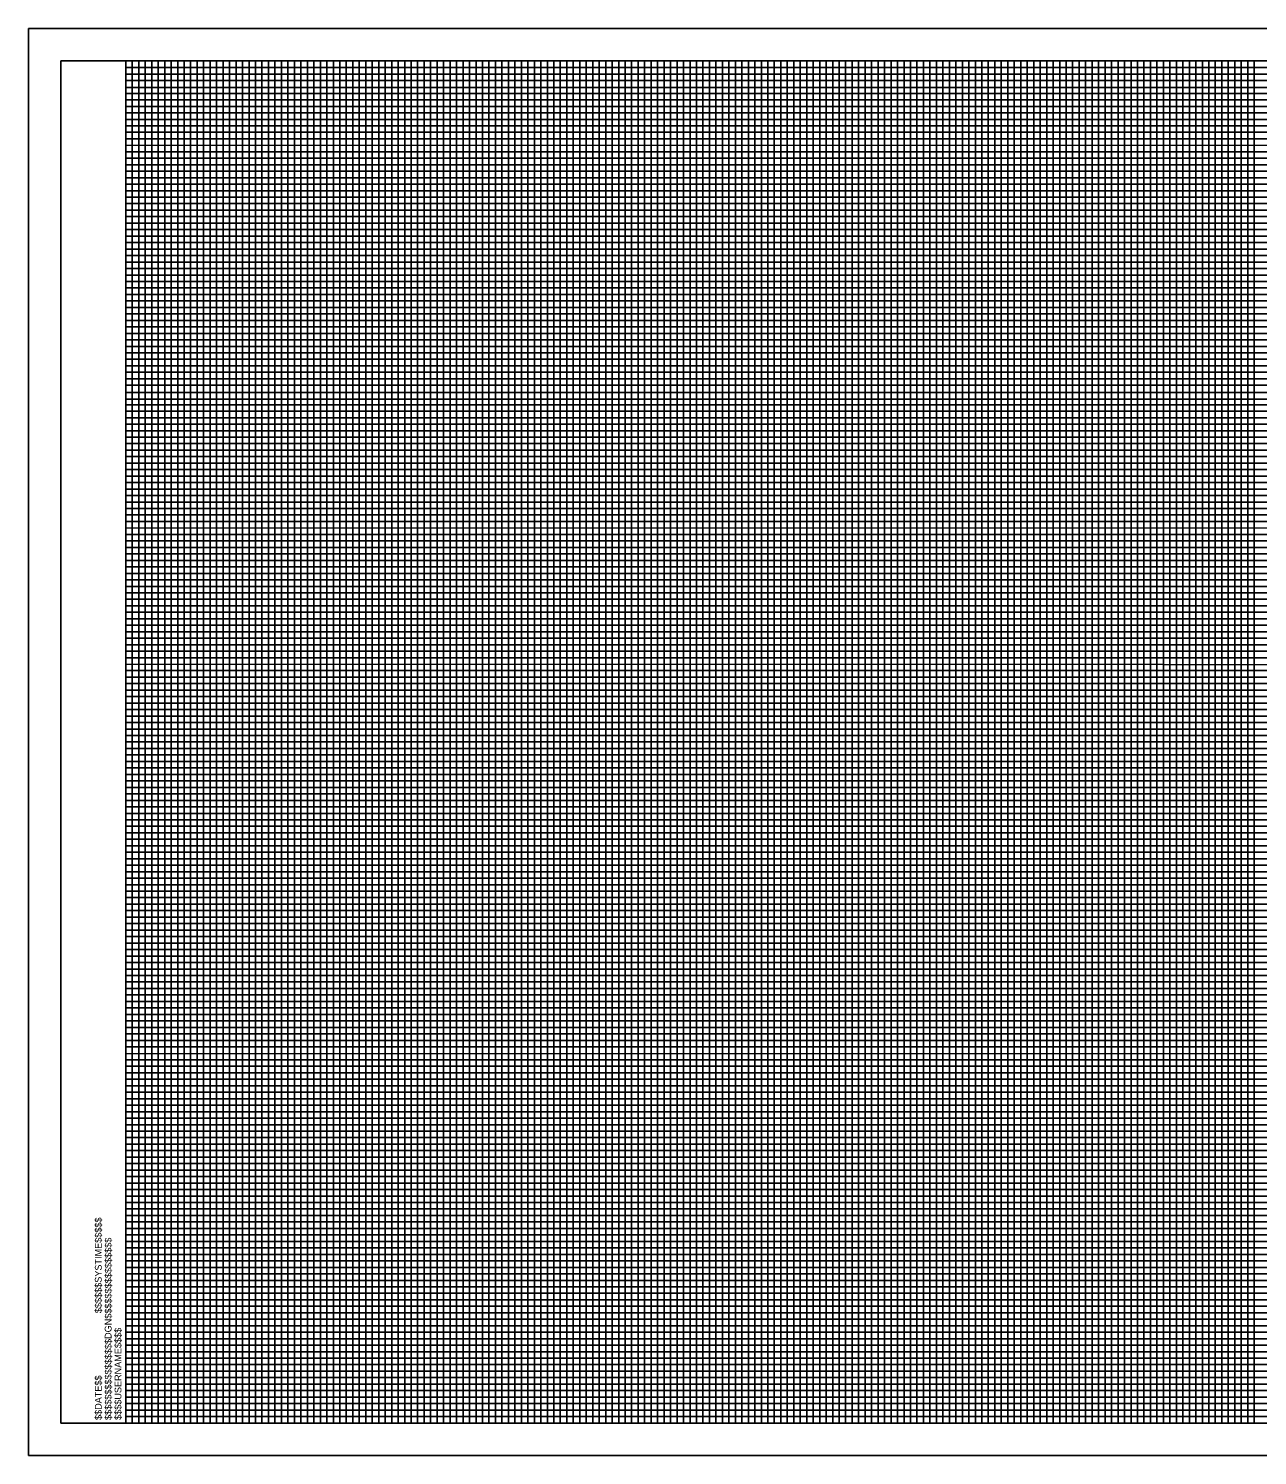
# Model space of a CAD drawing. Extents: x -1.5 to 36.6, y -0.5 to 21.5.
# Drawn here: x -1.5 to 17.45, y -0.5 to 21.5 of the extents above; entities that cross this region are included whole.
import ezdxf

# ---------------------------------------------------------------- set-up
doc = ezdxf.new("R2010")
doc.units = 0
for name, color, linetype in [('Old_Level_18', 7, 'Continuous'), ('Old_Level_38', 7, 'Continuous'), ('Old_Level_40', 7, 'Continuous'), ('Old_Level_41', 7, 'Continuous'), ('Old_Level_42', 7, 'Continuous'), ('Old_Level_43', 7, 'Continuous'), ('Old_Level_44', 7, 'Continuous'), ('Old_Level_62', 7, 'Continuous'), ('Old_Level_63', 7, 'Continuous')]:
    doc.layers.add(name, color=color, linetype=linetype)

msp = doc.modelspace()

# ---------------------------------------------------------------- linework, layer by layer
at = {"layer": 'Old_Level_18'}
msp.add_line((0, 0), (0, 0), dxfattribs=at)
msp.add_lwpolyline([(32, 21), (0, 21), (0, 0), (32, 0)], close=True, dxfattribs=at)
at = {"layer": 'Old_Level_38'}
msp.add_line((0, 0), (0, 0), dxfattribs=at)
at = {"layer": 'Old_Level_40'}
msp.add_line((0, 0), (0, 0), dxfattribs=at)
msp.add_line((0, 0), (0, 0), dxfattribs=at)
msp.add_line((0, 0), (0, 0), dxfattribs=at)
msp.add_line((0, 0), (0, 0), dxfattribs=at)
msp.add_line((0, 0), (0, 0), dxfattribs=at)
at = {"layer": 'Old_Level_41'}
for p, q in [((1, 21), (0, 21)), ((1, 0), (1, 21)), ((3, 21), (2, 21)), ((2, 21), (2, 0)), ((3, 0), (3, 21)), ((5, 21), (4, 21)), ((4, 21), (4, 0)), ((5, 0), (5, 21)), ((7, 21), (6, 21)), ((6, 21), (6, 0)), ((7, 0), (7, 21)), ((9, 21), (8, 21)), ((8, 21), (8, 0)), ((9, 0), (9, 21)), ((11, 21), (10, 21)), ((10, 21), (10, 0)), ((11, 0), (11, 21)), ((13, 21), (12, 21)), ((12, 21), (12, 0)), ((13, 0), (13, 21)), ((15, 21), (14, 21)), ((14, 21), (14, 0)), ((15, 0), (15, 21)), ((17, 21), (16, 21)), ((16, 21), (16, 0)), ((17, 0), (17, 21)), ((2, 0), (1, 0)), ((4, 0), (3, 0)), ((6, 0), (5, 0)), ((8, 0), (7, 0)), ((10, 0), (9, 0)), ((12, 0), (11, 0)), ((14, 0), (13, 0)), ((16, 0), (15, 0)), ((18, 0), (17, 0))]:
    msp.add_line(p, q, dxfattribs=at)
for points in [[(0, 20), (32, 20), (32, 19), (0, 19)], [(0, 18), (32, 18), (32, 17), (0, 17)], [(0, 16), (32, 16), (32, 15), (0, 15)], [(0, 14), (32, 14), (32, 13), (0, 13)], [(0, 12), (32, 12), (32, 11), (0, 11)], [(0, 10), (32, 10), (32, 9), (0, 9)], [(0, 8), (32, 8), (32, 7), (0, 7)], [(0, 6), (32, 6), (32, 5), (0, 5)], [(0, 4), (32, 4), (32, 3), (0, 3)], [(0, 2), (32, 2), (32, 1), (0, 1)]]:
    msp.add_lwpolyline(points, dxfattribs=at)
at = {"layer": 'Old_Level_42'}
for points in [[(0, 21), (0.5, 21), (0.5, 0), (1.5, 0), (1.5, 21), (2.5, 21), (2.5, 0), (3.5, 0), (3.5, 21), (4.5, 21), (4.5, 0), (5.5, 0), (5.5, 21), (6.5, 21), (6.5, 0), (7.5, 0), (7.5, 21), (8.5, 21), (8.5, 0), (9.5, 0), (9.5, 21), (10.5, 21), (10.5, 0), (11.5, 0), (11.5, 21), (12.5, 21), (12.5, 0), (13.5, 0), (13.5, 21), (14.5, 21), (14.5, 0), (15.5, 0), (15.5, 21), (16.5, 21), (16.5, 0), (17.5, 0)], [(0, 20.5), (26, 20.5)], [(0, 18.5), (32, 18.5), (32, 19.5), (0, 19.5)], [(0, 16.5), (32, 16.5), (32, 17.5), (0, 17.5)], [(0, 14.5), (32, 14.5), (32, 15.5), (0, 15.5)], [(0, 12.5), (32, 12.5), (32, 13.5), (0, 13.5)], [(0, 10.5), (32, 10.5), (32, 11.5), (0, 11.5)], [(0, 8.5), (32, 8.5), (32, 9.5), (0, 9.5)], [(0, 6.5), (32, 6.5), (32, 7.5), (0, 7.5)], [(0, 4.5), (32, 4.5), (32, 5.5), (0, 5.5)], [(0, 2.5), (32, 2.5), (32, 3.5), (0, 3.5)], [(0, 0.5), (32, 0.5), (32, 1.5), (0, 1.5)]]:
    msp.add_lwpolyline(points, dxfattribs=at)
at = {"layer": 'Old_Level_43'}
for p, q in [((0, 20.9), (26, 20.9)), ((26, 20.798), (0, 20.798)), ((0, 20.798), (0, 20.7)), ((0, 20.7), (26, 20.7)), ((26, 20.589), (0, 20.589)), ((0, 20.589), (0, 20.4)), ((0, 20.4), (32, 20.4))]:
    msp.add_line(p, q, dxfattribs=at)
for points in [[(0.5, 0), (0.6, 0), (0.6, 21), (0.7, 21), (0.7, 0)], [(0, 20.3), (32, 20.3)], [(32, 20.25), (32, 20.2), (0, 20.2)], [(0, 20.1), (32, 20.1), (32, 19.9), (0, 19.9)], [(0, 19.8), (32, 19.8), (32, 19.7), (0, 19.698)], [(0, 19.6), (32, 19.6), (32, 19.4), (0, 19.4)], [(0, 19.3), (32, 19.3), (32, 19.2), (0, 19.2)], [(0, 19.1), (32, 19.1), (32, 18.9), (0, 18.9)], [(0, 18.8), (32, 18.8), (32, 18.7), (0, 18.7)], [(0, 18.6), (32, 18.6), (32, 18.4), (0, 18.4)], [(0, 18.3), (32, 18.3), (32, 18.2), (0, 18.2)], [(0, 18.1), (32, 18.1), (32, 17.9), (0, 17.9)], [(0, 17.8), (32, 17.8), (32, 17.7), (0, 17.7)], [(0, 17.6), (32, 17.6), (32, 17.395), (32, 17.3), (32, 17.2), (0, 17.2)], [(0, 17.4), (32, 17.4), (32, 17.3), (0, 17.3)], [(0, 17.1), (32, 17.1), (32, 16.9), (0, 16.903)], [(0, 16.903), (32, 16.9), (32, 16.8), (0, 16.8)], [(0, 16.7), (32, 16.7), (32, 16.6), (0, 16.6)], [(0, 16.4), (32, 16.4), (32, 16.3), (0, 16.3)], [(0, 16.2), (32, 16.2), (32, 16.1), (0, 16.1)], [(-0.007, 15.889), (32, 15.889), (32, 15.788), (-0.007, 15.788)], [(0, 15.7), (32, 15.7), (32, 15.6), (0, 15.6)], [(0, 15.4), (32, 15.4), (32, 15.3), (0, 15.3)], [(0, 15.2), (32, 15.2), (32, 15.1), (0, 15.1)], [(0, 14.9), (32, 14.9), (32, 14.8), (0, 14.8)], [(0, 14.7), (32, 14.7), (32, 14.6), (0, 14.6)], [(0, 14.4), (32, 14.4), (32, 14.3), (0, 14.3)], [(0, 14.2), (32, 14.2), (32, 14.1), (0, 14.1)], [(0, 13.9), (32, 13.9), (31.999, 13.798), (0, 13.8)], [(0, 13.7), (32, 13.7), (32, 13.6), (0, 13.6)], [(0, 13.4), (32, 13.4), (32, 13.3), (0, 13.3)], [(0, 13.2), (32, 13.2), (32, 13.1), (0, 13.1)], [(0, 12.9), (32, 12.9), (32, 12.8), (0, 12.8)], [(0, 12.7), (32, 12.7), (32, 12.6), (0, 12.6)], [(0, 12.4), (32, 12.4), (32, 12.3), (0, 12.3)], [(0, 12.2), (32, 12.2), (32, 12.1), (0, 12.1)], [(0, 11.9), (32, 11.9), (32, 11.8), (0, 11.8)], [(0, 11.699), (32.007, 11.691), (32, 11.6), (0, 11.6)], [(0, 11.4), (32, 11.4), (32, 11.3), (0, 11.3)], [(0, 11.2), (32, 11.2), (32, 11.1), (0, 11.1)], [(0, 10.9), (32, 10.9), (32, 10.8), (0, 10.8)], [(0, 10.7), (32, 10.7), (32, 10.6), (0, 10.6)], [(0, 10.4), (32, 10.4), (32, 10.3), (0, 10.3)], [(0, 10.2), (32, 10.2), (32, 10.1), (0, 10.1)], [(0, 9.9), (32, 9.9), (32, 9.8), (0, 9.8)], [(0, 9.7), (32, 9.7), (32, 9.6), (0, 9.6)], [(0, 9.4), (32, 9.4), (32, 9.3), (0, 9.3)], [(0, 9.2), (32, 9.2), (32, 9.1), (0, 9.1)], [(0, 8.9), (32, 8.9), (32, 8.8), (0, 8.8)], [(0, 8.7), (32, 8.7), (32, 8.6), (0, 8.6)], [(0, 8.4), (32, 8.4), (32, 8.3), (0, 8.3)], [(0, 8.2), (32, 8.2), (32, 8.1), (0, 8.1)], [(0, 7.9), (32, 7.9), (31.999, 7.798), (0, 7.8)], [(0, 7.7), (32, 7.7), (32, 7.6), (0, 7.6)], [(0, 7.4), (32, 7.4), (32, 7.3), (0, 7.3)], [(0, 7.2), (32, 7.2), (32, 7.1), (0, 7.1)], [(0, 6.9), (32, 6.9), (32, 6.8), (0, 6.8)], [(0, 6.7), (32, 6.7), (32, 6.6), (0, 6.6)], [(0, 6.4), (32, 6.4), (32, 6.3), (0, 6.3)], [(0, 6.2), (32, 6.2), (32, 6.1), (0, 6.1)], [(0, 5.9), (32, 5.9), (32, 5.8), (0, 5.8)], [(0, 5.699), (32.007, 5.691), (32, 5.6), (0, 5.6)], [(0, 5.4), (32, 5.4), (32, 5.3), (0, 5.3)], [(0, 5.2), (32, 5.2), (32, 5.1), (0, 5.1)], [(0, 4.9), (32, 4.9), (32, 4.8), (0, 4.8)], [(0, 4.7), (32, 4.7), (32, 4.6), (0, 4.6)], [(0, 4.4), (32, 4.4), (32, 4.3), (0, 4.3)], [(0, 4.2), (32, 4.2), (32, 4.1), (0, 4.1)], [(0, 3.9), (32, 3.9), (32, 3.8), (0, 3.8)], [(0, 3.7), (32, 3.7), (32, 3.6), (0, 3.6)], [(0, 3.4), (32, 3.4), (32, 3.3), (0, 3.3)], [(0, 3.2), (32, 3.2), (32, 3.1), (0, 3.1)], [(0, 2.9), (32, 2.9), (32, 2.8), (0, 2.8)], [(0, 2.7), (32, 2.7), (32, 2.6), (0, 2.6)], [(0, 2.4), (32, 2.4), (32, 2.3), (0, 2.3)], [(0, 2.2), (32, 2.2), (32, 2.1), (0, 2.1)], [(0, 1.9), (32, 1.9), (32, 1.8), (0, 1.8)], [(0, 1.7), (32, 1.7), (32, 1.6), (0, 1.6)], [(0, 1.4), (32, 1.4), (32, 1.3), (0, 1.3)], [(0, 1.2), (32, 1.2), (32, 1.1), (0, 1.1)], [(0, 0.9), (32, 0.9), (32, 0.8), (0, 0.8)], [(0, 0.7), (32, 0.7), (32, 0.6), (0, 0.6)], [(0, 0.4), (32, 0.4), (32, 0.3), (0, 0.3)], [(0, 0.2), (32, 0.2), (32, 0.1), (0, 0.1)]]:
    msp.add_lwpolyline(points, dxfattribs=at)
at = {"layer": 'Old_Level_44'}
for points in [[(0, 0), (0.1, 0), (0.1, 21), (0.2, 21), (0.2, 0)], [(0.2, 0), (0.3, 0), (0.3, 21), (0.4, 21), (0.4, 0)], [(0.7, 0), (0.8, 0), (0.8, 21), (0.9, 21), (0.9, 0)], [(1, 0), (1.1, 0), (1.1, 21), (1.2, 21), (1.2, 0)], [(1.2, 0), (1.3, 0), (1.3, 21), (1.4, 21), (1.4, 0)], [(1.5, 0), (1.6, 0), (1.6, 21), (1.7, 21), (1.7, 0)], [(1.7, 0), (1.8, 0), (1.8, 21), (1.9, 21), (1.9, 0)], [(2, 0), (2.1, 0), (2.1, 21), (2.2, 21), (2.2, 0)], [(2.2, 0), (2.3, 0), (2.3, 21), (2.4, 21), (2.4, 0)], [(2.5, 0), (2.6, 0), (2.6, 21), (2.7, 21), (2.7, 0)], [(2.7, 0), (2.8, 0), (2.8, 21), (2.9, 21), (2.9, 0)], [(3, 0), (3.1, 0), (3.1, 21), (3.2, 21), (3.2, 0)], [(3.2, 0), (3.3, 0), (3.3, 21), (3.4, 21), (3.4, 0)], [(3.5, 0), (3.6, 0), (3.6, 21), (3.7, 21), (3.7, 0)], [(3.7, 0), (3.8, 0), (3.8, 21), (3.9, 21), (3.9, 0)], [(4, 0), (4.1, 0), (4.1, 21), (4.2, 21), (4.2, 0)], [(4.2, 0), (4.3, 0), (4.3, 21), (4.4, 21), (4.4, 0)], [(4.5, 0), (4.6, 0), (4.6, 21), (4.7, 21), (4.7, 0)], [(4.7, 0), (4.8, 0), (4.8, 21), (4.9, 21), (4.9, 0)], [(5, 0), (5.1, 0), (5.1, 21), (5.2, 21), (5.2, 0)], [(5.2, 0), (5.3, 0), (5.3, 21), (5.4, 21), (5.4, 0)], [(5.5, 0), (5.6, 0), (5.6, 21), (5.7, 21), (5.7, 0)], [(5.7, 0), (5.8, 0), (5.8, 21), (5.9, 21), (5.9, 0)], [(6, 0), (6.1, 0), (6.1, 21), (6.2, 21), (6.2, 0)], [(6.2, 0), (6.3, 0), (6.3, 21), (6.4, 21), (6.4, 0)], [(6.5, 0), (6.6, 0), (6.6, 21), (6.7, 21), (6.7, 0)], [(6.7, 0), (6.8, 0), (6.8, 21), (6.9, 21), (6.9, 0)], [(7, 0), (7.1, 0), (7.1, 21), (7.2, 21), (7.2, 0)], [(7.2, 0), (7.3, 0), (7.3, 21), (7.4, 21), (7.4, 0)], [(7.5, 0), (7.6, 0), (7.6, 21), (7.7, 21), (7.7, 0)], [(7.7, 0), (7.8, 0), (7.8, 21), (7.9, 21), (7.9, 0)], [(8, 0), (8.1, 0), (8.1, 21), (8.2, 21), (8.2, 0)], [(8.2, 0), (8.3, 0), (8.3, 21), (8.4, 21), (8.4, 0)], [(8.5, 0), (8.6, 0), (8.6, 21), (8.7, 21), (8.7, 0)], [(8.7, 0), (8.8, 0), (8.8, 21), (8.9, 21), (8.9, 0)], [(9, 0), (9.1, 0), (9.1, 21), (9.2, 21), (9.2, 0)], [(9.2, 0), (9.3, 0), (9.3, 21), (9.4, 21), (9.4, 0)], [(9.5, 0), (9.6, 0), (9.6, 21), (9.7, 21), (9.7, 0)], [(9.7, 0), (9.8, 0), (9.8, 21), (9.9, 21), (9.9, 0)], [(10, 0), (10.1, 0), (10.1, 21), (10.2, 21), (10.2, 0)], [(10.2, 0), (10.3, 0), (10.3, 21), (10.4, 21), (10.4, 0)], [(10.5, 0), (10.6, 0), (10.6, 21), (10.7, 21), (10.7, 0)], [(10.7, 0), (10.8, 0), (10.8, 21), (10.9, 21), (10.9, 0)], [(11, 0), (11.1, 0), (11.1, 21), (11.2, 21), (11.2, 0)], [(11.2, 0), (11.3, 0), (11.3, 21), (11.4, 21), (11.4, 0)], [(11.5, 0), (11.6, 0), (11.6, 21), (11.7, 21), (11.7, 0)], [(11.7, 0), (11.8, 0), (11.8, 21), (11.9, 21), (11.9, 0)], [(12, 0), (12.1, 0), (12.1, 21), (12.2, 21), (12.2, 0)], [(12.2, 0), (12.3, 0), (12.3, 21), (12.4, 21), (12.4, 0)], [(12.5, 0), (12.6, 0), (12.6, 21), (12.7, 21), (12.7, 0)], [(12.7, 0), (12.8, 0), (12.8, 21), (12.9, 21), (12.9, 0)], [(13, 0), (13.1, 0), (13.1, 21), (13.2, 21), (13.2, 0)], [(13.2, 0), (13.3, 0), (13.3, 21), (13.4, 21), (13.4, 0)], [(13.5, 0), (13.6, 0), (13.6, 21), (13.7, 21), (13.7, 0)], [(13.7, 0), (13.8, 0), (13.8, 21), (13.9, 21), (13.9, 0)], [(14, 0), (14.1, 0), (14.1, 21), (14.2, 21), (14.2, 0)], [(14.2, 0), (14.3, 0), (14.3, 21), (14.4, 21), (14.4, 0)], [(14.5, 0), (14.6, 0), (14.6, 21), (14.7, 21), (14.7, 0)], [(14.7, 0), (14.8, 0), (14.8, 21), (14.9, 21), (14.9, 0)], [(15, 0), (15.1, 0), (15.1, 21), (15.2, 21), (15.2, 0)], [(15.2, 0), (15.3, 0), (15.3, 21), (15.4, 21), (15.4, 0)], [(15.5, 0), (15.6, 0), (15.6, 21), (15.7, 21), (15.7, 0)], [(15.7, 0), (15.8, 0), (15.8, 21), (15.9, 21), (15.9, 0)], [(16, 0), (16.1, 0), (16.1, 21), (16.2, 21), (16.2, 0)], [(16.2, 0), (16.3, 0), (16.3, 21), (16.4, 21), (16.4, 0)], [(16.5, 0), (16.6, 0), (16.6, 21), (16.7, 21), (16.7, 0)], [(16.7, 0), (16.8, 0), (16.8, 21), (16.9, 21), (16.9, 0)], [(17, 0), (17.1, 0), (17.1, 21), (17.2, 21), (17.2, 0)], [(17.2, 0), (17.3, 0), (17.3, 21), (17.4, 21), (17.4, 0)]]:
    msp.add_lwpolyline(points, dxfattribs=at)
at = {"layer": 'Old_Level_62'}
msp.add_lwpolyline([(-1, 21), (32, 21), (32, 0), (-1, 0)], close=True, dxfattribs=at)
at = {"layer": 'Old_Level_63'}
msp.add_lwpolyline([(-1.5, -0.5), (32.5, -0.5), (32.5, 21.5), (-1.5, 21.5)], close=True, dxfattribs=at)

# ---------------------------------------------------------------- texts
at = {"layer": 'Old_Level_41'}
for s, p in [('$$$$$$SYSTIME$$$$$', (-0.372, 1.694)), ('$$$$$$$$$$$$$$$$DGN$$$$$$$$$$$$$$$$', (-0.22, 0.047)), ('$$$$USERNAME$$$$', (-0.068, 0.048)), ('$$DATE$$', (-0.372, 0.047))]:
    msp.add_text(s, height=0.105, rotation=90, dxfattribs=at).set_placement(p)

doc.saveas('drawing.dxf')
